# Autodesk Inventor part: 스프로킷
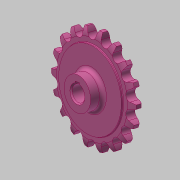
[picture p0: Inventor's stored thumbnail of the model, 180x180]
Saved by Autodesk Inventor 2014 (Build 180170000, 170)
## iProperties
Created: 2016-03
Part Number: 스프로킷
Material: 강철, 탄소
Document SubType Name: Modeling
Designer: mduedu
Density: 7.87 g/cm^3
Mass: 301.818 g
Surface Area: 124.882 cm^2
Volume: 38.3505 cm^3
Appearance: Pink
Author: mduedu
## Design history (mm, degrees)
sketch "스케치1"
  geometry: L1 (0, 5)-(29.5, 5); L2 (29.5, 5)-(29.5, 4.1); L3 (30, 3.6)-(33.625, 3.6); L4 (40, 2)-(40, 0); L5 (40, 0)-(0, 0); L6 (0, 0)-(0, 5); L7 (0, -5)-(29.5, -5); L8 (29.5, -5)-(29.5, -4.1); L9 (30, -3.6)-(33.625, -3.6); L10 (40, -2)-(40, 0); L11 (0, 0)-(0, -5); A1 r 13.5 centre (33.625, -9.9) between (40, 2) and (33.625, 3.6); A2 r 13.5 centre (33.625, 9.9) between (33.625, -3.6) and (40, -2); A3 r 0.5 centre (30, 4.1) between (29.5, 4.1) and (30, 3.6); A4 r 0.5 centre (30, -4.1) between (30, -3.6) and (29.5, -4.1); 2 further points
  constraints: 22 end point, 8 point on circle, 6 symmetric about line, 5 tangent, 4 centre point, 4 parallel, 4 point on line, 1 equal radius, 1 horizontal, 1 perpendicular, 1 other
  dimensions: "d0" = 80 diameter of L4 L6; "d2" = 59 diameter of L2 L6; "d3" = 1.6 vertical distance of L4.start L3.end; "d4" = 3.6 distance from line of L4.end L3; "d5" = 5 distance between parallel lines of L5 L1; "d6" = 13.5 radius of A1; "d15" = 0.5 radius of A3
revolve "회전1" sketch "스케치1" stored, may be unused: angle "d7" = 90 deg
sketch "스케치2" dims "d8" = 65.2, "d11" = 80
  geometry: L1 (0, 0)-(0, 32.6); A1 r 36.57 centre (0, 0) between (-16.231, 32.771) and (0, 36.57); A2 r 3.97 centre (0, 36.57) between (-3.866, 35.665) and (0, 32.6); A3 r 12.7 centre (-16.231, 32.771) between (-3.866, 35.665) and (-5.534, 39.615); A4 r 12.7 centre (16.231, 32.771) between (5.534, 39.615) and (3.866, 35.665); A5 r 3.97 centre (0, 36.57) between (0, 32.6) and (3.866, 35.665); A6 r 40 centre (0, 0) between (5.534, 39.615) and (-5.534, 39.615); 2 further points
  constraints: 12 point on circle, 6 centre point, 4 coincident, 3 symmetric about line, 2 end point, 1 point on line, 1 tangent, 1 vertical, 1 vertical alignment, 7 other
  dimensions: "d10" = 73.14 diameter of A1; "d12" = 12.7 radius of A3
extrude "돌출1" cut sketch "스케치2" stored distance "d13" = 10; taper "d14" = 0 deg
sketch "스케치3"
  geometry: C1 r 12.5 at (0, 0); 1 further point
  constraints: 1 centre point, 1 coincident
  dimensions: "d19" = 25 diameter of C1
extrude "돌출2" join sketch "스케치3" distance "d20" = 10; taper "d21" = 0 deg
fillet "모깎기1" dims "d22" = 3
sketch "스케치4"
  geometry: L1 (-2, 0)-(2, 0); L2 (2, 0)-(2, 7.8); L3 (2, 7.8)-(-2, 7.8); L4 (-2, 7.8)-(-2, 0); C1 r 6 at (0, 0); 2 further points
  constraints: 8 end point, 2 coincident, 2 parallel, 1 centre point, 1 horizontal, 1 midpoint, 1 perpendicular
  dimensions: "d23" = 12 diameter of C1; "d25" = 4 distance of L2.end L3.end; "d26" = 7.8 distance of L1.end L2.end
extrude "돌출3" cut sketch "스케치4" stored distance "d27" = 8; taper "d28" = 0 deg
chamfer "모따기2" distance "d42" = 1; stored, may be unused: second distance "d43" = 2, angle "d44" = 45 deg
node "솔리드1"
pattern_circular "원형 패턴1" dims angle "d17" = 360 deg
